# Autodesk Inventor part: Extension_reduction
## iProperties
Shininess: 64.0
Length Units: 11269
Angle Units: 11279
Time Units: 11290
Mass Units: 11283
Length Display Precision: 3
Angle Display Precision: 2
Compacted: True
Part Number: Extension_reduction
Document SubType Name: Modeling
Created: 2008-02
Material: Acier inoxydable, austénitique
Designer: Pascal
Density: 0.0
Volumn: 0.0
Area: 0.0
PropertySet Name: Model Information
Control State: 0
Master: False
Checked Out: False
DESIGNATION: Extension rectangulaire réduction
Author: Pascal
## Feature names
1. Extrusion1
2. Extrusion2
